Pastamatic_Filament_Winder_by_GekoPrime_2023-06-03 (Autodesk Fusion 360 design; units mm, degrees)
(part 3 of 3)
align "Align3"
move "Move2" TranslateX 0 TranslateY 0 TranslateZ -5.8 (= "-stack_unit / 2")
combine "Combine1"
extrude "Extrude60" sketch "Sketch8" profile of A1 A2 A3 L7 A4 A5 A6 A7 A8 L9 A9 A10 blind 16 (= "bearing_id * 2")
align "Align4"
combine "Combine2"
extrude "Extrude61" new body sketch "Sketch8" profile of L7 A4 A5 A6 L9 A9 A10 along normal blind 16 (= "bearing_id * 2")
align "Align5"
combine "Combine3"
chamfer "Chamfer18" distance 0.6667 (= "wall_thickness / 3")
offset_faces "OffsetFaces1"
extrude "Extrude73" new body sketch "Sketch1" profile of L7 A4 L14 L17 L31 L32 L33 A12 L45 L46 L47 L48 along normal blind 11.6 (= "stack_unit") bodies "wiper_mount_left"
sketch "Sketch13" plane through (24.4187, 0, 0) normal (1, 0, 0) x axis (0, 0, -1)
  line L1 (0, 144.049) -> (0, 124.978)
  line L2 (-11.6, 144.049) -> (0, 144.049)
  line L3 (-11.6, 124.978) -> (-11.6, 144.049)
  line L4 (0, 124.978) -> (-11.6, 124.978)
  line L5 (0, 58.3113) -> (-1, 58.3113)
  line L6 (0, 124.978) -> (0, 58.3113)
  line L7 (-1, 124.978) -> (0, 124.978)
  line L8 (-1, 58.3113) -> (-11.6, 58.3113)
  line L9 (-11.6, 58.3113) -> (-11.6, 124.978)
  line L10 (-11.6, 91.6446) -> (0, 91.6446)
  point P9 (0, 124.978)
  point P10 (0, 124.978)
  point P7 (-1, 58.3113)
  point P12 (-1, 58.3113)
  point P5 (-11.6, 124.978)
  point P13 (-11.6, 124.978)
  point P14 (0, 91.6446)
  point P15 (-11.6, 91.6446)
  point P8 (0, 58.3113)
  perpendicular L5 L6
  perpendicular L6 L7
  coincident P9 P10
  collinear L1 L6
  coincident P7 P12
  coincident P5 P13
  perpendicular L8 L9
  midpoint L6 P14
  midpoint L9 P15
  dimension "d1790" distance L4 P8 = 66.6667 (= "spool_od_bambu / 3")
extrude "Extrude74" sketch "Sketch13" profile of L4 L5 L6 L7 L8 to an object
sketch "Sketch14" plane through (0, 58.3113, 0) normal (0, -1, 0) x axis (1, 0, 0)
  line L1 (-24.4187, 0) -> (-24.4187, 11.6)
  line L2 (24.4187, 0) -> (-24.4187, 0)
  line L3 (24.4187, 11.6) -> (24.4187, 0)
  line L4 (-24.4187, 11.6) -> (24.4187, 11.6)
  line L5 (1.6971, 23.0752) -> (0, 11.6)
  line L6 (-0.8578, 5.8) -> (0, 11.6)
  line L7 (1.2328, 23.3532) -> (-1.2825, 6.3455)
  line L8 (2.222, 23.2069) -> (-0.2933, 6.1992)
  line L9 (-1.2825, 6.3455) -> (-0.2933, 6.1992)
  line L10 (2.222, 23.2069) -> (1.2328, 23.3532)
  line L11 (2.2444, 21.9905) -> (1.2328, 23.3532)
  line L12 (1.6353, 8.3557) -> (0.2867, 3.9841)
  line L13 (-0.2217, 3.2655) -> (-2.2002, 3.5581)
  line L14 (0.0407, 3.4603) -> (-0.2217, 3.2655)
  line L15 (-2.1671, 5.3975) -> (-1.7718, 5.6257)
  arc A1 centre (1.8005, 23.7747) radius 0.7071 clockwise from (1.2328, 23.3532) to (2.222, 23.2069)
  arc A2 centre (0.6959, 6.0529) radius 1 clockwise from (-0.0333, 5.3686) to (-0.2933, 6.1992)
  arc A3 centre (1.3684, 10.6) radius 1 clockwise from (0.3792, 10.7463) to (1.3684, 11.6)
  arc A4 centre (-1.6642, 10.6) radius 1 clockwise from (-1.6642, 11.6) to (-0.675, 10.4537)
  arc A5 centre (3.1652, 22.749) radius 1 clockwise from (2.1759, 22.8953) to (2.3658, 23.3498)
  arc A6 centre (0.1974, 23.1879) radius 1 clockwise from (1.1365, 23.5316) to (1.1867, 23.0416)
  arc A7 centre (-1.0647, 4.401) radius 1.4142 clockwise from (-0.0333, 5.3686) to (-1.7718, 5.6257)
  arc A8 centre (-2.2718, 6.4918) radius 1 clockwise from (-1.2825, 6.3455) to (-1.7718, 5.6257)
  point P6 (0, 11.6)
  point P12 (2.222, 23.2069)
  point P14 (2.222, 23.2069)
  point P7 (1.6971, 23.0752)
  point P13 (1.8005, 23.7747)
  point P15 (-0.7879, 6.2723)
  point P29 (2.1759, 22.8953)
  point P28 (2.3658, 23.3498)
  point P31 (1.1867, 23.0416)
  point P32 (1.1365, 23.5316)
  point P23 (0.3792, 10.7463)
  point P22 (1.3684, 11.6)
  point P26 (-1.6642, 11.6)
  point P25 (-0.675, 10.4537)
  point P19 (-0.2933, 6.1992)
  point P33 (-1.0647, 4.401)
  point P11 (-0.2933, 6.1992)
  point P34 (0.2867, 3.9841)
  point P8 (-0.8578, 5.8)
  point P36 (-2.2002, 3.5581)
  point P37 (-0.2217, 3.2655)
  point P9 (-1.2825, 6.3455)
  point P40 (-1.2825, 6.3455)
  point P10 (1.2328, 23.3532)
  midpoint L4 P6
  coincident P12 P14
  coincident P7 A1
  coincident L5 P13
  midpoint L9 P15
  coincident L6 P15
  perpendicular L6 L9
  perpendicular L8 L9
  perpendicular L5 L10
  tangent A1 L11
  coincident L8 P29
  coincident A1 P28
  coincident L7 P31
  coincident A1 P32
  coincident L8 P23
  coincident L4 P22
  coincident L4 P26
  coincident L7 P25
  coincident L8 P19
  tangent L8 A2
  equal A3 A4
  tangent A1 A6
  tangent L8 A5
  tangent A1 A5
  equal A5 A6
  equal A3 A5
  equal A2 A3
  tangent L4 A4
  tangent L7 A4
  tangent L4 A3
  tangent L8 A3
  tangent L7 A6
  coincident L6 P33
  tangent A2 A7
  coincident P11 P19
  coincident A7 P34
  tangent A7 L12
  collinear L5 L6
  coincident P8 A7
  coincident A7 P36
  coincident A7 P37
  tangent A7 L14
  perpendicular L6 L13
  coincident P9 P40
  tangent L7 A8
  tangent A7 A8
  tangent A7 L15
  dimension "d1810" distance L1 L3 = 48.8375
  dimension "d1816" distance P10 P14 = 1
  dimension "d1817" angle L7 L11 = 45
  dimension "d1818" distance P6 P7 = 11.6 (= "stack_unit")
  dimension "d1837" distance L4 P8 = 5.8 (= "stack_unit / 2")
  dimension "d1838" radius A5 = 1 (= "wall_thickness / 2")
  dimension "d1839" angle L6 L14 = 45
  dimension "d1843" distance P36 P37 = 2 (= "wall_thickness")
  dimension "d1844" angle L4 L15 = 30
extrude "Extrude75" cut sketch "Sketch14" profile of L4 L7 L8 A1 A2 A3 A4 A5 A6 A7 L13 A8 against normal blind 66.6667 (magnitude of "-spool_od_bambu / 3")
chamfer "Chamfer19" distance 0.5 (= "wall_thickness / 4")
rectangular_pattern "R-Pattern2" uSpaceDistance 20 (= "( 40 / 2 ) * 1 mm") vSpaceDistance 0
fillet "Fillet23" radius 2 (= "wall_thickness")
mirror "Mirror7" mirrorStitchTolerance 0.1 bodies "wiper_mount_right"
extrude "Extrude76" new body sketch "Sketch14" profile of L4 L7 L8 A1 A2 A7 L13 A8 to an object bodies "wiper_blade_tpu"
sketch "Sketch16" plane through (0, 0, -11.6) normal (0, 0, -1) x axis (-1, 0, 0)
  line L1 (-183.0785, 143.3824) -> (-182.4118, 144.049)
  line L2 (-183.0785, 108.049) -> (-183.0785, 143.3824)
  line L3 (-30.6569, 22.24) -> (-11.98, 40.9168)
  line L4 (-21.6788, -11.5706) -> (-32.3575, 13.4419)
  line L5 (-14, 0) -> (-14, -10)
  line L6 (14, -10) -> (14, 0)
  line L7 (32.3575, 13.4419) -> (21.6788, -11.5706)
  line L8 (18.3848, 118.5932) -> (-1.6205, 98.5879)
  line L9 (24.4187, 144.049) -> (24.4187, 131.5812)
  line L10 (7.0711, 144.049) -> (24.4187, 144.049)
  line L11 (4.1421, 126.978) -> (7.0711, 129.9069)
  line L12 (-4.1421, 126.978) -> (4.1421, 126.978)
  line L13 (-7.0711, 129.9069) -> (-4.1421, 126.978)
  line L14 (-182.4118, 144.049) -> (-7.0711, 144.049)
  curve K1
  curve K2
  curve K3
  curve K4
  line L15 (-120.9635, 75.7732) -> (-120.9635, 93.5653)
  line L16 (-104.9635, 91.3632) -> (-104.9635, 75.7732)
  arc A1 centre (-175.0785, 108.049) radius 8 clockwise from (-172.1153, 100.618) to (-183.0785, 108.049)
  arc A2 centre (-118.7313, -33.2588) radius 144.1279 clockwise from (-172.1153, 100.618) to (-139.2402, 109.4025)
  arc A3 centre (-23.2937, 52.2305) radius 16 clockwise from (-11.3759, 62.906) to (-11.98, 40.9168)
  arc A4 centre (-25, 16.5831) radius 8 clockwise from (-32.3575, 13.4419) to (-30.6569, 22.24)
  arc A5 centre (-18, -10) radius 4 clockwise from (-14, -10) to (-21.6788, -11.5706)
  arc A6 centre (0, 0) radius 14 clockwise from (-14, 0) to (14, 0)
  arc A7 centre (18, -10) radius 4 clockwise from (21.6788, -11.5706) to (14, -10)
  arc A8 centre (25, 16.5831) radius 8 clockwise from (32.5584, 19.2042) to (32.3575, 13.4419)
  arc A9 centre (-118.7313, -33.2588) radius 160.1279 clockwise from (-1.9733, 76.3246) to (32.5584, 19.2042)
  arc A10 centre (9.6932, 87.2742) radius 16 clockwise from (-1.9733, 76.3246) to (-1.6205, 98.5879)
  arc A11 centre (0, 136.978) radius 26 clockwise from (21.8887, 122.9464) to (18.3848, 118.5932)
  arc A12 centre (8.4187, 131.5812) radius 16 clockwise from (24.4187, 131.5812) to (21.8887, 122.9464)
  arc A13 centre (0, 136.978) radius 10 clockwise from (7.0711, 144.049) to (7.0711, 129.9069)
  arc A14 centre (0, 136.978) radius 10 clockwise from (-7.0711, 129.9069) to (-7.0711, 144.049)
  circle C1 centre (25, 16.5831) radius 4.15
  circle C2 centre (7.04, 52.3244) radius 4.15
  circle C3 centre (-25, 16.5831) radius 4.15
  circle C4 centre (-62.3842, 108.049) radius 4.15
  circle C5 centre (-19.6153, 82.1488) radius 4.15
  circle C6 centre (-175.0785, 108.049) radius 4.15
  arc A15 centre (-112.9635, 75.7732) radius 8 clockwise from (-104.9635, 75.7732) to (-120.9635, 75.7732)
  circle C7 centre (-112.9635, 75.7732) radius 4.15
  arc A16 centre (-136.9635, 93.5653) radius 16 clockwise from (-139.2402, 109.4025) to (-120.9635, 93.5653)
  arc A17 centre (-88.9635, 91.3632) radius 16 clockwise from (-104.9635, 91.3632) to (-85.2462, 106.9254)
  arc A18 centre (-118.7313, -33.2588) radius 144.1279 clockwise from (-85.2462, 106.9254) to (-11.3759, 62.906)
  point P2 (-182.4118, 144.049)
  point P40 (-7.0711, 144.049)
  coincident P2
  coincident P40
  tangent A2 K3
  dimension "d1845" Text1-Height = 20
emboss "Emboss4" sketch "Sketch16" Depth -0.16 Horizontal Distance 0 Vertical Distance 0 Rotation Angle 0
joint_origin "JointOrigin20"
joint_origin "JointOrigin19"
joint_origin "JointOrigin21"
joint_origin "JointOrigin23"
joint_origin "JointOrigin24"
joint_origin "JointOrigin25"
joint_origin "JointOrigin26"
joint_origin "JointOrigin44"
joint_origin "JointOrigin45"
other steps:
base_feature "Base Feature3" bodies "spur_gear_30t_7mm"
base_feature "Base Feature4" bodies "spur_gear_50t_7mm (1)"
base_feature "Base Feature12" bodies "spool_passive", "spool_passive_long"
base_feature "Base Feature11" bodies "spool_active", "spindle_male_passive"
base_feature "Base Feature10" bodies "spur_gear_10t_7mm"
base_feature "紁ऀ" bodies "spur_gear_10t_7mm", "double_idler"
create_component "CreateComponent25"
create_component "CreateComponent37"
create_component "CreateComponent38"
create_component "CreateComponent39"
create_component "CreateComponent40"
create_component "CreateComponent41"
create_component "CreateComponent42"
create_component "CreateComponent43"
create_component "CreateComponent45"
create_component "CreateComponent47"
named bodies: "groove", "leadscrew_tooth", "idler", "spur_gear_40t_7mm", "leadscrew_pin", "spool_active_bolt", "nut_negative", "spindle_male_driven", "nut_positive", "spindle_female", "spur_gear_10t_7mm", "spur_gear_50t_7mm", "spool_cap", "cradle_crossbar", "spur_gear_50t_7mm (1)", "leadscrew_block", "driven_target_cradle", "double_idler", "source_cradle", "spur_gear_10t_14mm_6mmD", "spur_gear_30t_7mm", "pin_long", "pin_short", "spool_active", "spindle_male_passive", "spool_passive", "spool_passive_long", "leadscrew", "wiper_mount_left", "wiper_mount_right", "wiper_blade_tpu", "passive_target_cradle"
